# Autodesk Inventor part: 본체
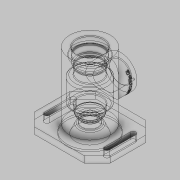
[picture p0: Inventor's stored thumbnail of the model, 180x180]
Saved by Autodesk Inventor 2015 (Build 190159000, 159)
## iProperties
Created: 2017-10
Part Number: 본체
Material: 일반
Document SubType Name: Modeling
Designer: SCD-A15
Density: 1 g/cm^3
Appearance: 기본값
Author: SCD-A15
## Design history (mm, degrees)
sketch "스케치1"
  geometry: L1 (31, 57.5)-(0, 57.5); L2 (0, 57.5)-(0, -57.5); L3 (0, -57.5)-(31, -57.5); L4 (31, -57.5)-(31, 57.5); 2 further points
  constraints: 8 end point, 2 coincident, 2 parallel, 1 horizontal, 1 midpoint, 1 perpendicular
  dimensions: "d0" = 115 distance of L3.end L1.start; "d2" = 62 diameter of L4 L2
revolve "회전1" sketch "스케치1" stored, may be unused: angle "d3" = 90 deg
sketch "스케치2"
  geometry: L1 (-58, 47)-(58, 47); L2 (58, 47)-(58, -47); L3 (58, -47)-(-58, -47); L4 (-58, -47)-(-58, 47); C1 r 31 at (0, 0) reference; 2 further points
  constraints: 8 end point, 2 midpoint, 2 parallel, 1 horizontal, 1 horizontal alignment, 1 perpendicular, 1 vertical alignment
  dimensions: "d5" = 116 distance of L1.start L1.end; "d6" = 94 distance of L3.end L1.start
extrude "돌출1" join sketch "스케치2" distance "d7" = 13; taper "d8" = 0 deg
sketch "스케치3"
  geometry: L1 (0, 0)-(116, 0) reference; L2 (0, -94)-(0, 0) reference; L3 (116, -94)-(0, -94) reference; L4 (116, 0)-(116, -94) reference; C1 r 35 at (58, -47); 1 further point
  constraints: 1 centre point, 1 coincident
  dimensions: "d9" = 70 diameter of C1
extrude "돌출2" cut sketch "스케치3" distance "d10" = 3; taper "d11" = 0 deg
node "작업 평면2"
  node "작업 평면1"
sketch "스케치4"
  geometry: L1 (89, -102)-(27, -102) reference; C1 r 25 at (58, -46); 2 further points
  constraints: 1 centre point, 1 midpoint, 1 vertical alignment
  dimensions: "d13" = 50 diameter of C1; "d14" = 56 distance from line of L1 C1.centre
extrude "돌출3" join sketch "스케치4" stored distance "d15" = 47 (= d12); taper "d16" = 0 deg
sketch "스케치5" dims "d17" = 8, "d18" = 8
  geometry: L1 (46.253, 16.008)-(46.154, 16.008); L2 (46.154, -16.003)-(46.253, -16.003); C1 r 31 at (0, 0) reference; 2 further points
  constraints: 4 end point, 1 horizontal, 1 parallel, 1 vertical alignment, 6 other
  dimensions: "d19" = 46 horizontal distance of C1.centre point (46, -20); "d20" = 20 vertical distance of C1.centre point (46, -20); "d22" = 20 vertical distance of point (46, 20) C1.centre
extrude "돌출4" cut sketch "스케치5" distance "d23" = 47 (= d12); taper "d24" = 0 deg
sketch "스케치6"
  geometry: L1 (42, 20)-(50, 20); L2 (50, 20)-(50, -20); L3 (50, -20)-(42, -20); L4 (42, -20)-(42, 20); 2 further points
  constraints: 8 end point, 2 horizontal alignment, 2 parallel, 1 horizontal, 1 perpendicular, 2 other
extrude "돌출5" cut sketch "스케치6" distance "d25" = 47 (= d12); taper "d26" = 0 deg
hole "구멍1" diameter "d29" = 40.376; stored, may be unused: countersink angle "d33" = 90 deg, drill point angle "d35" = 0 deg; dims "d30" = 84, "d31" = 4, "d32" = 2, "d34" = 9, "d55" = 10, "d56" = 10
hole "구멍2" diameter "d38" = 48; stored, may be unused: countersink angle "d42" = 90 deg, drill point angle "d44" = 0 deg; dims "d36" = 10, "d37" = 10, "d39" = 84, "d40" = 4, "d41" = 2, "d43" = 3
sketch "스케치9"
  geometry: L1 (-35, -57.5)-(-35, -54.5) reference; L2 (-35, -54.5)-(-47, -54.5) reference; L3 (-47, -54.5)-(-47, -44.5) reference; L4 (-47, -44.5)-(-31, -44.5) reference; L5 (-31, -44.5)-(-31, 57.5) reference; L6 (-31, 57.5)-(-20.188, 57.5) reference; L7 (-20.188, 57.5)-(-20.188, 48.5) reference; L8 (-20.188, 48.5)-(-24, 48.5) reference; L9 (-24, 48.5)-(-24, 45.5) reference; L10 (-24, 45.5)-(24, 45.5) reference; L11 (24, 45.5)-(24, 48.5) reference; L12 (24, 48.5)-(20.188, 48.5) reference; L13 (20.188, 48.5)-(20.188, 57.5) reference; L14 (20.188, 57.5)-(31, 57.5) reference; L15 (31, 57.5)-(31, 26.5) reference; L16 (31, 26.5)-(47, 26.5) reference; L17 (47, 26.5)-(47, -23.5) reference; L18 (47, -23.5)-(31, -23.5) reference; L19 (31, -23.5)-(31, -44.5) reference; L20 (31, -44.5)-(47, -44.5) reference; L21 (47, -44.5)-(47, -54.5) reference; L22 (47, -54.5)-(35, -54.5) reference; L23 (35, -54.5)-(35, -57.5) reference; L24 (35, -57.5)-(-35, -57.5) reference; L25 (20, 45.5)-(20, 36.5); L26 (20, 36.5)-(17.5, 36.5); L27 (17.5, 36.5)-(17.5, 33.25); L28 (0, 45.5)-(0, -57.5); L29 (17.5, 33.25)-(18.5, 33.25); L30 (18.5, 33.25)-(18.5, 31.5); L31 (18.5, 31.5)-(17.5, 31.5); L32 (17.5, 31.5)-(17.5, 20.5); L33 (17.5, 20.5)-(26, 20.5); L34 (26, 20.5)-(26, -17.5); L35 (26, -17.5)-(17.5, -17.5); L36 (17.5, -17.5)-(17.5, -28.5); L37 (17.5, -28.5)-(16.5, -28.5); L38 (16.5, -28.5)-(16.5, -33.5); L39 (16.5, -33.5)-(10, -33.5); L40 (10, -33.5)-(10, -36.2); L41 (10, -36.2)-(12.5, -36.2); L42 (12.5, -36.2)-(12.5, -43.5); L43 (12.904, -43.5)-(16, -43.5); L44 (16, -43.5)-(22, -57.5); L45 (12.5, -42.8)-(12.904, -43.5); 1 further point
  constraints: 42 end point, 11 perpendicular, 6 horizontal, 3 point on line, 2 midpoint, 1 vertical
  dimensions: "d47" = 40 diameter of L25 L28; "d48" = 35 diameter of L27 L28; "d49" = 9 distance of L25.start L25.end; "d50" = 3.25 distance of L26.end L27.end; "d51" = 1.75 distance of L29.end L30.end; "d52" = 37 diameter of L30 L28; "d53" = 11 distance of L31.end L32.end; "d54" = 35 diameter of L32 L28; "d59" = 38 distance of L33.end L34.end; "d60" = 52 diameter of L34 L28; "d61" = 35 diameter of L36 L28; "d62" = 11 distance of L35.end L36.end; "d63" = 5 distance of L37.end L38.end; "d64" = 33 diameter of L38 L28; "d66" = 2.7 distance of L39.end L40.end; "d67" = 20 diameter of L40 L28; "d68" = 25 diameter of L42 L28; "d69" = 7.3 distance of L41.end L42.end; "d70" = 32 diameter of L43.end L28; "d71" = 44 diameter of L44.end L28; "d72" = 0.7 distance from line of L43 L45.start; "d73" = 30 deg angle of L42 L45
revolve "회전2" sketch "스케치9" stored, may be unused: angle "d74" = 90 deg
sketch "스케치10"
  geometry: C1 r 25 at (0, 0) reference; C2 r 16 at (0, 0); 1 further point
  constraints: 1 centre point, 1 coincident
  dimensions: "d75" = 32 diameter of C2
extrude "돌출6" cut sketch "스케치10" stored distance "d76" = 47 (= d12); taper "d77" = 0 deg
sketch "스케치12"
  geometry: L1 (31, -56)-(-31, -56) reference; C1 r 16 at (0, 0) reference; 3 further points
  dimensions: "d82" = 20.5 distance of C1.centre point (-20.5, 0); "d83" = 56 distance from line of L1 point (-20.5, 0); "d84" = 20.5 distance of C1.centre point (20.5, 0); "d85" = 56 distance from line of L1 point (20.5, 0)
hole "구멍3" sketch "스케치12" at (-20.5, 0), (20.5, 0) diameter "d86" = 2.459; stored, may be unused: countersink angle "d90" = 90 deg, drill point angle "d92" = 118 deg; dims "d87" = 6, "d88" = 4, "d89" = 2, "d91" = 8
node "작업 평면3"
sketch "스케치13"
  geometry: L1 (-31, 57.5)-(31, 57.5) reference; L2 (47, 26.5)-(47, -23.5) reference; 2 further points
  constraints: 1 other
  dimensions: "d94" = 56 distance from line of L1 point (37, 1.5); "d95" = 10 distance from line of L2 point (37, 1.5)
feature "엠보싱1" sketch "스케치13" dims "d0" = 115, "d2" = 62, "d96" = 0.5, "d97" = 0
chamfer "모따기1" distance "d78" = 20; stored, may be unused: second distance "d79" = 2, angle "d80" = 45 deg
chamfer "모따기2" distance "d98" = 1; stored, may be unused: second distance "d99" = 2, angle "d100" = 45 deg
fillet "모깎기1" dims "d101" = 2
fillet "모깎기2" dims "d102" = 3
chamfer "모따기3" distance "d103" = 1; stored, may be unused: second distance "d104" = 2, angle "d105" = 45 deg
fillet "모깎기3" dims "d106" = 0.3
fillet "모깎기4" dims "d107" = 0.3
node "솔리드1"
mirror "대칭1"
node "절단 모서리 투영1"
other parameters: "d12" = 47, "d93" = 81.5
